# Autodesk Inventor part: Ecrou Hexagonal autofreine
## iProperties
Created: 2002-05
Part Number: Ecrou Hexagonal autofreine
Material: Par défaut
Catalog Web Link: www.traceparts.com
Description: Ecrou Hexagonal DIN 6924 - M 12 x 1,75 - 6
Document SubType Name: Modélisation
Designer: REVEST Pierre
Control State: 0
Master: False
Checked Out: False
Shininess: 60.0
Length Units: 11269
Angle Units: 11279
Time Units: 11290
Mass Units: 11283
Length Display Precision: 3
Angle Display Precision: 2
Density: 0.0
Volumn: 0.0
Area: 0.0
PropertySet Name: Model Information
Author: REVEST Pierre
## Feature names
1. Base1
